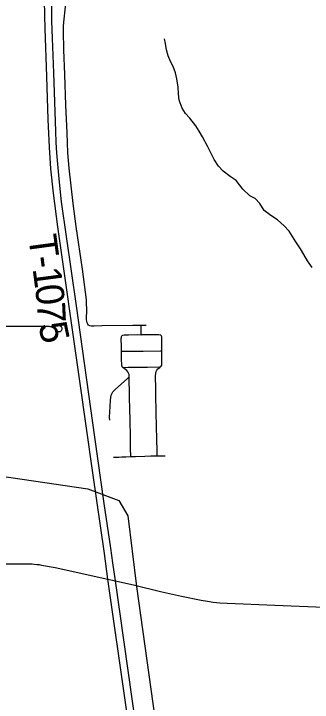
# Model space of a CAD drawing. Extents: x 0 to 34, y -5 to 22.
# Drawn here: x 5.234 to 5.836, y 15.13 to 16.518 of the extents above; entities that cross this region are included whole.
import ezdxf

# ---------------------------------------------------------------- set-up
doc = ezdxf.new("R2010")
doc.units = 0
for name, color, linetype in [('GM_X_Minor_River', 7, 'Continuous'), ('GM_X_Rail_Line', 7, 'Continuous'), ('GM_X_State_Route', 7, 'Continuous'), ('GM_X_Township_Road', 7, 'Continuous'), ('GM_X_Township_Road_Text', 7, 'Continuous')]:
    doc.layers.add(name, color=color, linetype=linetype)

msp = doc.modelspace()

# ---------------------------------------------------------------- linework, layer by layer
at = {"layer": 'GM_X_Minor_River'}
msp.add_lwpolyline([(5.8357, 16.0065), (5.8262, 16.0201), (5.8185, 16.033), (5.8116, 16.0447), (5.8027, 16.0583), (5.7958, 16.0693), (5.7889, 16.0799), (5.779, 16.0908), (5.7656, 16.1029), (5.7519, 16.1119), (5.7389, 16.1216), (5.7301, 16.1356), (5.7205, 16.1458), (5.7099, 16.1514), (5.6958, 16.1646), (5.6823, 16.1824), (5.6701, 16.1906), (5.6557, 16.2008), (5.6469, 16.2113), (5.638, 16.2246), (5.6311, 16.2378), (5.6242, 16.2514), (5.6142, 16.2703), (5.6076, 16.2817), (5.6007, 16.2923), (5.5885, 16.3078), (5.5801, 16.3176), (5.5735, 16.3282), (5.567, 16.3441), (5.5657, 16.357), (5.5653, 16.3706), (5.5629, 16.3873), (5.5601, 16.3991), (5.5551, 16.412), (5.5497, 16.4222), (5.5451, 16.4339), (5.5416, 16.4457), (5.5396, 16.4582), (5.538, 16.468)], dxfattribs=at)
at = {"layer": 'GM_X_Rail_Line'}
msp.add_lwpolyline([(4.2939, 16.5478), (4.428, 16.1111), (4.4985, 16.0565), (5.0896, 15.6072), (5.1407, 15.5965), (5.3829, 15.5608), (5.4458, 15.537), (5.4636, 15.5061), (5.4813, 15.3635), (5.5596, 14.8004), (5.5691, 14.7552), (5.5999, 14.7267)], dxfattribs=at)
at = {"layer": 'GM_X_State_Route'}
for points in [[(5.2964, 16.5144), (5.2959, 16.5475), (5.2957, 16.5583)], [(5.5227, 14.7863), (5.505, 14.9109), (5.4881, 15.0278), (5.4646, 15.194), (5.4387, 15.3749), (5.4335, 15.4116), (5.4292, 15.4408), (5.4161, 15.531), (5.3973, 15.6649), (5.36, 15.9296), (5.3304, 16.1389), (5.3252, 16.1853), (5.3231, 16.2079), (5.3208, 16.238), (5.3196, 16.2589), (5.3187, 16.2815), (5.3145, 16.3995), (5.3117, 16.4694), (5.3107, 16.5035), (5.3105, 16.5288), (5.3103, 16.5523), (5.3103, 16.5583)], [(5.6059, 14.1), (5.6056, 14.1025), (5.601, 14.1339), (5.5958, 14.1714), (5.5496, 14.4959), (5.5422, 14.5468), (5.5374, 14.582), (5.5337, 14.6061), (5.4753, 15.0177), (5.4303, 15.3315), (5.4238, 15.3782), (5.4165, 15.43), (5.3932, 15.5931), (5.367, 15.7778), (5.3228, 16.0887), (5.3139, 16.1564), (5.3088, 16.2059), (5.3057, 16.2493), (5.3034, 16.3051), (5.3002, 16.3921), (5.2969, 16.4884), (5.2964, 16.5144)]]:
    msp.add_lwpolyline(points, dxfattribs=at)
at = {"layer": 'GM_X_Township_Road'}
msp.add_line((5.5005, 15.8897), (5.4906, 15.8898), dxfattribs=at)
for points in [[(5.3829, 15.8929), (5.3817, 15.8955), (5.381, 15.8984), (5.3807, 15.9014), (5.3811, 15.9234), (5.3808, 15.9339), (5.3802, 15.9417), (5.3782, 15.9573), (5.3722, 16.0035), (5.3595, 16.0897), (5.3535, 16.1359), (5.3453, 16.2069), (5.3427, 16.2378), (5.3412, 16.2782), (5.3391, 16.3341), (5.3369, 16.3961), (5.3346, 16.4458), (5.3339, 16.483), (5.3342, 16.493), (5.3349, 16.5016), (5.3379, 16.5324), (5.3393, 16.5507), (5.3397, 16.5584)], [(5.1989, 15.8885), (5.2648, 15.8884), (5.3052, 15.8883), (5.3066, 15.8882), (5.3076, 15.8881), (5.3083, 15.8879), (5.3092, 15.8877), (5.3102, 15.8873), (5.3111, 15.8868), (5.3121, 15.8862), (5.3137, 15.8851), (5.3183, 15.8809), (5.3196, 15.8798), (5.3207, 15.879), (5.3214, 15.8786), (5.322, 15.8783), (5.3227, 15.878), (5.3233, 15.8778), (5.3241, 15.8777), (5.325, 15.8776), (5.3257, 15.8776), (5.3264, 15.8777), (5.3271, 15.8778), (5.3278, 15.878), (5.3286, 15.8784), (5.3293, 15.8789), (5.3303, 15.8798), (5.3309, 15.8809), (5.3313, 15.8822), (5.3314, 15.883), (5.3313, 15.8838), (5.3313, 15.8846), (5.3309, 15.8858), (5.3304, 15.8867), (5.3299, 15.8872), (5.3293, 15.8878), (5.3286, 15.8882), (5.328, 15.8885), (5.3274, 15.8889), (5.3266, 15.8892), (5.3257, 15.8894), (5.3249, 15.8895), (5.3243, 15.8896), (5.3235, 15.8896), (5.3218, 15.8896), (5.32, 15.8895), (5.3181, 15.8894), (5.3135, 15.8892), (5.3127, 15.889), (5.3117, 15.8886), (5.3099, 15.8877)], [(5.4906, 15.8898), (5.4893, 15.8898), (5.4737, 15.8898), (5.4115, 15.8895), (5.396, 15.8888), (5.3899, 15.8888), (5.3871, 15.8894), (5.3848, 15.8909), (5.3829, 15.8929)], [(5.4697, 15.6256), (5.4697, 15.6285), (5.4695, 15.64), (5.4692, 15.6487), (5.469, 15.6606), (5.4682, 15.704), (5.4678, 15.7162), (5.4672, 15.7504), (5.4668, 15.7845), (5.4667, 15.7861), (5.4662, 15.7908), (5.4652, 15.7939), (5.4637, 15.7968), (5.4617, 15.7994), (5.4567, 15.8035), (5.4539, 15.8055), (5.4527, 15.8066), (5.4521, 15.808), (5.4518, 15.8094), (5.4513, 15.8227), (5.451, 15.8383), (5.4508, 15.847), (5.4506, 15.8636), (5.4508, 15.8659), (5.451, 15.8677), (5.4517, 15.869), (5.4526, 15.8698), (5.4539, 15.8703), (5.4563, 15.8709), (5.4593, 15.871), (5.4654, 15.871), (5.4841, 15.8715), (5.4906, 15.8714), (5.4907, 15.8782), (5.4906, 15.8845), (5.4906, 15.8898)], [(5.5229, 15.6273), (5.5228, 15.6345), (5.5221, 15.6635), (5.5217, 15.6835), (5.5207, 15.7173), (5.5202, 15.7478), (5.52, 15.7628), (5.5197, 15.7875), (5.5202, 15.7938), (5.5209, 15.797), (5.5224, 15.8), (5.5245, 15.8026), (5.5282, 15.8054), (5.5295, 15.8065), (5.5303, 15.807), (5.5313, 15.8081), (5.5321, 15.8097), (5.5324, 15.8116), (5.5324, 15.8142), (5.5324, 15.817), (5.5324, 15.8353), (5.5324, 15.8385), (5.5323, 15.8447), (5.5325, 15.854), (5.5326, 15.8601), (5.5325, 15.8634), (5.5324, 15.8669), (5.532, 15.8687), (5.5313, 15.8697), (5.5304, 15.8703), (5.5292, 15.8707), (5.5265, 15.8712), (5.5174, 15.8713), (5.5082, 15.8711), (5.502, 15.8711), (5.4906, 15.8714)], [(5.451, 15.8383), (5.454, 15.8383), (5.4665, 15.8383), (5.4947, 15.8383), (5.5295, 15.8385), (5.5324, 15.8385)], [(5.4539, 15.8055), (5.4552, 15.8054), (5.4643, 15.8057), (5.4795, 15.8059), (5.5037, 15.8062), (5.5278, 15.8064), (5.5295, 15.8065)], [(5.4273, 15.6992), (5.427, 15.7052), (5.4279, 15.7266), (5.4288, 15.7388), (5.4295, 15.7447), (5.4305, 15.7495), (5.4321, 15.7536), (5.4338, 15.756), (5.4357, 15.7582), (5.4384, 15.7606), (5.4634, 15.7832), (5.4667, 15.7861)], [(5.4349, 15.6243), (5.4456, 15.6245), (5.4517, 15.6248), (5.4596, 15.6251), (5.4697, 15.6256), (5.4794, 15.626), (5.4979, 15.6266), (5.5099, 15.627), (5.5212, 15.6272), (5.5229, 15.6273), (5.5301, 15.6272), (5.5391, 15.6272)], [(5.1481, 15.4093), (5.1499, 15.4093), (5.192, 15.4091), (5.2241, 15.4095), (5.2554, 15.4097), (5.2711, 15.4091), (5.2752, 15.4089), (5.2806, 15.4082), (5.2849, 15.4077), (5.2897, 15.4069), (5.3173, 15.4018), (5.3629, 15.3922), (5.4083, 15.3817), (5.4238, 15.3782)], [(5.4238, 15.3782), (5.4295, 15.3769), (5.4387, 15.3749), (5.4781, 15.3663), (5.5295, 15.3539), (5.572, 15.3444), (5.6115, 15.3363), (5.6247, 15.3339), (5.6361, 15.3324), (5.6491, 15.331), (5.6638, 15.3302), (5.7601, 15.326), (5.8594, 15.3218), (5.9432, 15.3181), (5.9867, 15.3159), (6.0488, 15.3127), (6.1047, 15.3092), (6.1388, 15.3071), (6.1441, 15.3068)]]:
    msp.add_lwpolyline(points, dxfattribs=at)

# ---------------------------------------------------------------- texts
at = {"layer": 'GM_X_Township_Road_Text'}
for s, rotation, p in [('T', 277.6943, (5.2629, 16.0697)), ('-', 277.6488, (5.2686, 16.0275)), ('1', 277.5046, (5.2717, 16.0045)), ('0', 276.9385, (5.2763, 15.9699)), ('7', 272.7436, (5.2804, 15.9363)), ('5', 281.7579, (5.2833, 15.8916))]:
    msp.add_text(s, height=0.0568, rotation=rotation, dxfattribs=at).set_placement(p)

doc.saveas('drawing.dxf')
